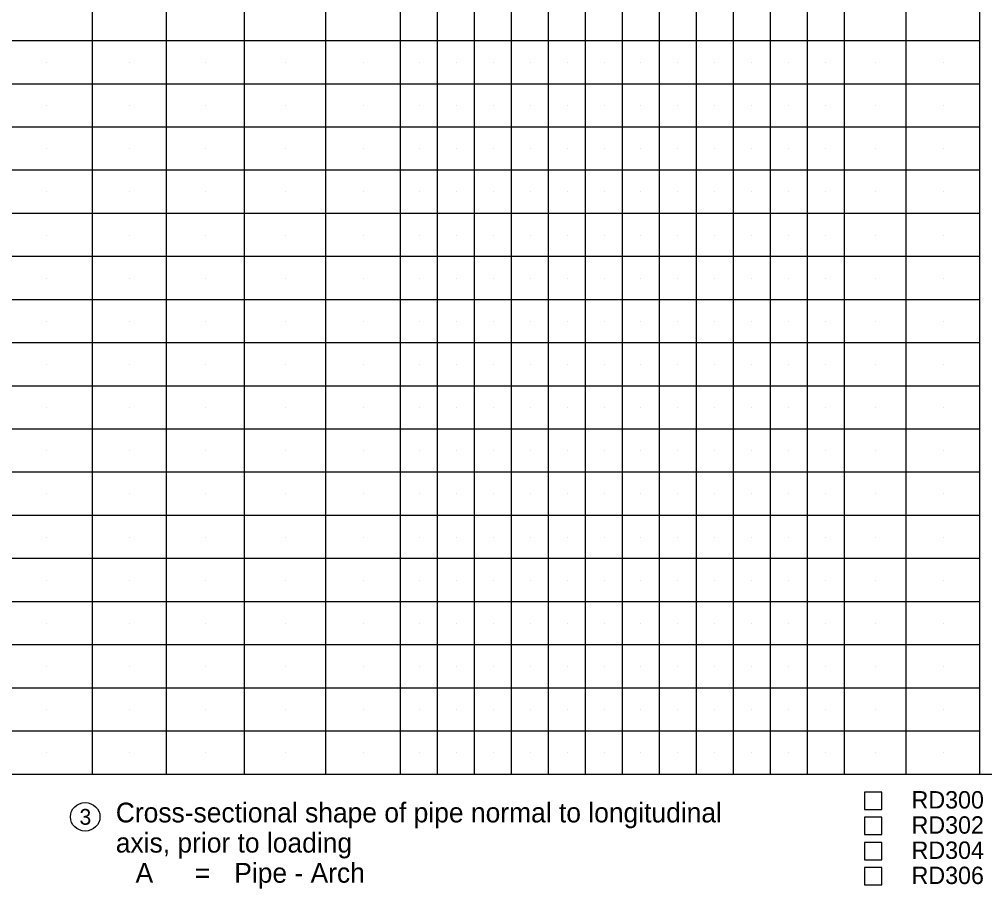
# Model space of a CAD drawing. Extents: x 0 to 1.42, y 0 to 0.92.
# Drawn here: x 0.2562 to 0.5109, y 0.2302 to 0.4596 of the extents above; entities that cross this region are included whole.
import ezdxf

# ---------------------------------------------------------------- set-up
doc = ezdxf.new("R2010")
doc.units = 0
doc.layers.add('P_ODOT_PLAN_General', color=7, linetype='Continuous')
doc.layers.add('P_RDWY_PLAN_NotesTx', color=7, linetype='Continuous')

msp = doc.modelspace()

# ---------------------------------------------------------------- linework, layer by layer
at = {"layer": 'P_ODOT_PLAN_General'}
for p, q in [((0.35681, 0.26037), (0.35681, 0.875)), ((0.50965, 0.26037), (0.50965, 0.875)), ((0.36656, 0.26037), (0.36656, 0.86199)), ((0.37632, 0.26037), (0.37632, 0.86199)), ((0.38608, 0.26037), (0.38608, 0.86199)), ((0.39583, 0.26037), (0.39583, 0.86199)), ((0.40559, 0.26037), (0.40559, 0.86199)), ((0.41534, 0.26037), (0.41534, 0.86199)), ((0.4251, 0.26037), (0.4251, 0.86199)), ((0.43486, 0.26037), (0.43486, 0.86199)), ((0.44461, 0.26037), (0.44461, 0.86199)), ((0.45437, 0.26037), (0.45437, 0.86199)), ((0.46412, 0.26037), (0.46412, 0.86199)), ((0.47388, 0.26037), (0.47388, 0.86199)), ((0.49014, 0.26037), (0.49014, 0.86199)), ((0.27551, 0.26037), (0.27551, 0.84573)), ((0.29502, 0.26037), (0.29502, 0.84573)), ((0.33711, 0.26037), (0.33711, 0.7937)), ((0.31564, 0.26037), (0.31564, 0.76118)), ((0.50965, 0.45387), (0.25112, 0.45387)), ((0.26331, 0.44818), (0.26331, 0.44818)), ((0.28526, 0.44818), (0.28526, 0.44818)), ((0.30533, 0.44818), (0.30533, 0.44818)), ((0.32637, 0.44818), (0.32637, 0.44818)), ((0.34696, 0.44818), (0.34696, 0.44818)), ((0.36169, 0.44818), (0.36169, 0.44818)), ((0.37144, 0.44818), (0.37144, 0.44818)), ((0.3812, 0.44818), (0.3812, 0.44818)), ((0.39095, 0.44818), (0.39095, 0.44818)), ((0.40071, 0.44818), (0.40071, 0.44818)), ((0.41047, 0.44818), (0.41047, 0.44818)), ((0.42022, 0.44818), (0.42022, 0.44818)), ((0.42998, 0.44818), (0.42998, 0.44818)), ((0.43973, 0.44818), (0.43973, 0.44818)), ((0.44949, 0.44818), (0.44949, 0.44818)), ((0.45925, 0.44818), (0.45925, 0.44818)), ((0.469, 0.44818), (0.469, 0.44818)), ((0.48201, 0.44818), (0.48201, 0.44818)), ((0.4999, 0.44818), (0.4999, 0.44818)), ((0.50965, 0.44248), (0.25112, 0.44248)), ((0.26331, 0.43679), (0.26331, 0.43679)), ((0.28526, 0.43679), (0.28526, 0.43679)), ((0.30533, 0.43679), (0.30533, 0.43679)), ((0.32637, 0.43679), (0.32637, 0.43679)), ((0.34696, 0.43679), (0.34696, 0.43679)), ((0.36169, 0.43679), (0.36169, 0.43679)), ((0.37144, 0.43679), (0.37144, 0.43679)), ((0.3812, 0.43679), (0.3812, 0.43679)), ((0.39095, 0.43679), (0.39095, 0.43679)), ((0.40071, 0.43679), (0.40071, 0.43679)), ((0.41047, 0.43679), (0.41047, 0.43679)), ((0.42022, 0.43679), (0.42022, 0.43679)), ((0.42998, 0.43679), (0.42998, 0.43679)), ((0.43973, 0.43679), (0.43973, 0.43679)), ((0.44949, 0.43679), (0.44949, 0.43679)), ((0.45925, 0.43679), (0.45925, 0.43679)), ((0.469, 0.43679), (0.469, 0.43679)), ((0.48201, 0.43679), (0.48201, 0.43679)), ((0.4999, 0.43679), (0.4999, 0.43679)), ((0.50965, 0.4311), (0.25112, 0.4311)), ((0.26331, 0.42541), (0.26331, 0.42541)), ((0.28526, 0.42541), (0.28526, 0.42541)), ((0.30533, 0.42541), (0.30533, 0.42541)), ((0.32637, 0.42541), (0.32637, 0.42541)), ((0.34696, 0.42541), (0.34696, 0.42541)), ((0.36169, 0.42541), (0.36169, 0.42541)), ((0.37144, 0.42541), (0.37144, 0.42541)), ((0.3812, 0.42541), (0.3812, 0.42541)), ((0.39095, 0.42541), (0.39095, 0.42541)), ((0.40071, 0.42541), (0.40071, 0.42541)), ((0.41047, 0.42541), (0.41047, 0.42541)), ((0.42022, 0.42541), (0.42022, 0.42541)), ((0.42998, 0.42541), (0.42998, 0.42541)), ((0.43973, 0.42541), (0.43973, 0.42541)), ((0.44949, 0.42541), (0.44949, 0.42541)), ((0.45925, 0.42541), (0.45925, 0.42541)), ((0.469, 0.42541), (0.469, 0.42541)), ((0.48201, 0.42541), (0.48201, 0.42541)), ((0.4999, 0.42541), (0.4999, 0.42541)), ((0.50965, 0.41972), (0.25112, 0.41972)), ((0.26331, 0.41403), (0.26331, 0.41403)), ((0.28526, 0.41403), (0.28526, 0.41403)), ((0.30533, 0.41403), (0.30533, 0.41403)), ((0.32637, 0.41403), (0.32637, 0.41403)), ((0.34696, 0.41403), (0.34696, 0.41403)), ((0.36169, 0.41403), (0.36169, 0.41403)), ((0.37144, 0.41403), (0.37144, 0.41403)), ((0.3812, 0.41403), (0.3812, 0.41403)), ((0.39095, 0.41403), (0.39095, 0.41403)), ((0.40071, 0.41403), (0.40071, 0.41403)), ((0.41047, 0.41403), (0.41047, 0.41403)), ((0.42022, 0.41403), (0.42022, 0.41403)), ((0.42998, 0.41403), (0.42998, 0.41403)), ((0.43973, 0.41403), (0.43973, 0.41403)), ((0.44949, 0.41403), (0.44949, 0.41403)), ((0.45925, 0.41403), (0.45925, 0.41403)), ((0.469, 0.41403), (0.469, 0.41403)), ((0.48201, 0.41403), (0.48201, 0.41403)), ((0.4999, 0.41403), (0.4999, 0.41403)), ((0.50965, 0.40834), (0.25112, 0.40834)), ((0.26331, 0.40265), (0.26331, 0.40265)), ((0.28526, 0.40265), (0.28526, 0.40265)), ((0.30533, 0.40265), (0.30533, 0.40265)), ((0.32637, 0.40265), (0.32637, 0.40265)), ((0.34696, 0.40265), (0.34696, 0.40265)), ((0.36169, 0.40265), (0.36169, 0.40265)), ((0.37144, 0.40265), (0.37144, 0.40265)), ((0.3812, 0.40265), (0.3812, 0.40265)), ((0.39095, 0.40265), (0.39095, 0.40265)), ((0.40071, 0.40265), (0.40071, 0.40265)), ((0.41047, 0.40265), (0.41047, 0.40265)), ((0.42022, 0.40265), (0.42022, 0.40265)), ((0.42998, 0.40265), (0.42998, 0.40265)), ((0.43973, 0.40265), (0.43973, 0.40265)), ((0.44949, 0.40265), (0.44949, 0.40265)), ((0.45925, 0.40265), (0.45925, 0.40265)), ((0.469, 0.40265), (0.469, 0.40265)), ((0.48201, 0.40265), (0.48201, 0.40265)), ((0.4999, 0.40265), (0.4999, 0.40265)), ((0.50965, 0.39696), (0.25112, 0.39696)), ((0.26331, 0.39127), (0.26331, 0.39127)), ((0.28526, 0.39127), (0.28526, 0.39127)), ((0.30533, 0.39127), (0.30533, 0.39127)), ((0.32637, 0.39127), (0.32637, 0.39127)), ((0.34696, 0.39127), (0.34696, 0.39127)), ((0.36169, 0.39127), (0.36169, 0.39127)), ((0.37144, 0.39127), (0.37144, 0.39127)), ((0.3812, 0.39127), (0.3812, 0.39127)), ((0.39095, 0.39127), (0.39095, 0.39127)), ((0.40071, 0.39127), (0.40071, 0.39127)), ((0.41047, 0.39127), (0.41047, 0.39127)), ((0.42022, 0.39127), (0.42022, 0.39127)), ((0.42998, 0.39127), (0.42998, 0.39127)), ((0.43973, 0.39127), (0.43973, 0.39127)), ((0.44949, 0.39127), (0.44949, 0.39127)), ((0.45925, 0.39127), (0.45925, 0.39127)), ((0.469, 0.39127), (0.469, 0.39127)), ((0.48201, 0.39127), (0.48201, 0.39127)), ((0.4999, 0.39127), (0.4999, 0.39127)), ((0.50965, 0.38557), (0.25112, 0.38557)), ((0.26331, 0.37988), (0.26331, 0.37988)), ((0.28526, 0.37988), (0.28526, 0.37988)), ((0.30533, 0.37988), (0.30533, 0.37988)), ((0.32637, 0.37988), (0.32637, 0.37988)), ((0.34696, 0.37988), (0.34696, 0.37988)), ((0.36169, 0.37988), (0.36169, 0.37988)), ((0.37144, 0.37988), (0.37144, 0.37988)), ((0.3812, 0.37988), (0.3812, 0.37988)), ((0.39095, 0.37988), (0.39095, 0.37988)), ((0.40071, 0.37988), (0.40071, 0.37988)), ((0.41047, 0.37988), (0.41047, 0.37988)), ((0.42022, 0.37988), (0.42022, 0.37988)), ((0.42998, 0.37988), (0.42998, 0.37988)), ((0.43973, 0.37988), (0.43973, 0.37988)), ((0.44949, 0.37988), (0.44949, 0.37988)), ((0.45925, 0.37988), (0.45925, 0.37988)), ((0.469, 0.37988), (0.469, 0.37988)), ((0.48201, 0.37988), (0.48201, 0.37988)), ((0.4999, 0.37988), (0.4999, 0.37988)), ((0.50965, 0.37419), (0.25112, 0.37419)), ((0.26331, 0.3685), (0.26331, 0.3685)), ((0.28526, 0.3685), (0.28526, 0.3685)), ((0.30533, 0.3685), (0.30533, 0.3685)), ((0.32637, 0.3685), (0.32637, 0.3685)), ((0.34696, 0.3685), (0.34696, 0.3685)), ((0.36169, 0.3685), (0.36169, 0.3685)), ((0.37144, 0.3685), (0.37144, 0.3685)), ((0.3812, 0.3685), (0.3812, 0.3685)), ((0.39095, 0.3685), (0.39095, 0.3685)), ((0.40071, 0.3685), (0.40071, 0.3685)), ((0.41047, 0.3685), (0.41047, 0.3685)), ((0.42022, 0.3685), (0.42022, 0.3685)), ((0.42998, 0.3685), (0.42998, 0.3685)), ((0.43973, 0.3685), (0.43973, 0.3685)), ((0.44949, 0.3685), (0.44949, 0.3685)), ((0.45925, 0.3685), (0.45925, 0.3685)), ((0.469, 0.3685), (0.469, 0.3685)), ((0.48201, 0.3685), (0.48201, 0.3685)), ((0.4999, 0.3685), (0.4999, 0.3685)), ((0.50965, 0.36281), (0.25112, 0.36281)), ((0.26331, 0.35712), (0.26331, 0.35712)), ((0.28526, 0.35712), (0.28526, 0.35712)), ((0.30533, 0.35712), (0.30533, 0.35712)), ((0.32637, 0.35712), (0.32637, 0.35712)), ((0.34696, 0.35712), (0.34696, 0.35712)), ((0.36169, 0.35712), (0.36169, 0.35712)), ((0.37144, 0.35712), (0.37144, 0.35712)), ((0.3812, 0.35712), (0.3812, 0.35712)), ((0.39095, 0.35712), (0.39095, 0.35712)), ((0.40071, 0.35712), (0.40071, 0.35712)), ((0.41047, 0.35712), (0.41047, 0.35712)), ((0.42022, 0.35712), (0.42022, 0.35712)), ((0.42998, 0.35712), (0.42998, 0.35712)), ((0.43973, 0.35712), (0.43973, 0.35712)), ((0.44949, 0.35712), (0.44949, 0.35712)), ((0.45925, 0.35712), (0.45925, 0.35712)), ((0.469, 0.35712), (0.469, 0.35712)), ((0.48201, 0.35712), (0.48201, 0.35712)), ((0.4999, 0.35712), (0.4999, 0.35712)), ((0.50965, 0.35143), (0.25112, 0.35143)), ((0.26331, 0.34574), (0.26331, 0.34574)), ((0.28526, 0.34574), (0.28526, 0.34574)), ((0.30533, 0.34574), (0.30533, 0.34574)), ((0.32637, 0.34574), (0.32637, 0.34574)), ((0.34696, 0.34574), (0.34696, 0.34574)), ((0.36169, 0.34574), (0.36169, 0.34574)), ((0.37144, 0.34574), (0.37144, 0.34574)), ((0.3812, 0.34574), (0.3812, 0.34574)), ((0.39095, 0.34574), (0.39095, 0.34574)), ((0.40071, 0.34574), (0.40071, 0.34574)), ((0.41047, 0.34574), (0.41047, 0.34574)), ((0.42022, 0.34574), (0.42022, 0.34574)), ((0.42998, 0.34574), (0.42998, 0.34574)), ((0.43973, 0.34574), (0.43973, 0.34574)), ((0.44949, 0.34574), (0.44949, 0.34574)), ((0.45925, 0.34574), (0.45925, 0.34574)), ((0.469, 0.34574), (0.469, 0.34574)), ((0.48201, 0.34574), (0.48201, 0.34574)), ((0.4999, 0.34574), (0.4999, 0.34574)), ((0.50965, 0.34005), (0.25112, 0.34005)), ((0.26331, 0.33436), (0.26331, 0.33436)), ((0.28526, 0.33436), (0.28526, 0.33436)), ((0.30533, 0.33436), (0.30533, 0.33436)), ((0.32637, 0.33436), (0.32637, 0.33436)), ((0.34696, 0.33436), (0.34696, 0.33436)), ((0.36169, 0.33436), (0.36169, 0.33436)), ((0.37144, 0.33436), (0.37144, 0.33436)), ((0.3812, 0.33436), (0.3812, 0.33436)), ((0.39095, 0.33436), (0.39095, 0.33436)), ((0.40071, 0.33436), (0.40071, 0.33436)), ((0.41047, 0.33436), (0.41047, 0.33436)), ((0.42022, 0.33436), (0.42022, 0.33436)), ((0.42998, 0.33436), (0.42998, 0.33436)), ((0.43973, 0.33436), (0.43973, 0.33436)), ((0.44949, 0.33436), (0.44949, 0.33436)), ((0.45925, 0.33436), (0.45925, 0.33436)), ((0.469, 0.33436), (0.469, 0.33436)), ((0.48201, 0.33436), (0.48201, 0.33436)), ((0.4999, 0.33436), (0.4999, 0.33436)), ((0.50965, 0.32866), (0.25112, 0.32866)), ((0.26331, 0.32297), (0.26331, 0.32297)), ((0.28526, 0.32297), (0.28526, 0.32297)), ((0.30533, 0.32297), (0.30533, 0.32297)), ((0.32637, 0.32297), (0.32637, 0.32297)), ((0.34696, 0.32297), (0.34696, 0.32297)), ((0.36169, 0.32297), (0.36169, 0.32297)), ((0.37144, 0.32297), (0.37144, 0.32297)), ((0.3812, 0.32297), (0.3812, 0.32297)), ((0.39095, 0.32297), (0.39095, 0.32297)), ((0.40071, 0.32297), (0.40071, 0.32297)), ((0.41047, 0.32297), (0.41047, 0.32297)), ((0.42022, 0.32297), (0.42022, 0.32297)), ((0.42998, 0.32297), (0.42998, 0.32297)), ((0.43973, 0.32297), (0.43973, 0.32297)), ((0.44949, 0.32297), (0.44949, 0.32297)), ((0.45925, 0.32297), (0.45925, 0.32297)), ((0.469, 0.32297), (0.469, 0.32297)), ((0.48201, 0.32297), (0.48201, 0.32297)), ((0.4999, 0.32297), (0.4999, 0.32297)), ((0.50965, 0.31728), (0.25112, 0.31728)), ((0.26331, 0.31159), (0.26331, 0.31159)), ((0.28526, 0.31159), (0.28526, 0.31159)), ((0.30533, 0.31159), (0.30533, 0.31159)), ((0.32637, 0.31159), (0.32637, 0.31159)), ((0.34696, 0.31159), (0.34696, 0.31159)), ((0.36169, 0.31159), (0.36169, 0.31159)), ((0.37144, 0.31159), (0.37144, 0.31159)), ((0.3812, 0.31159), (0.3812, 0.31159)), ((0.39095, 0.31159), (0.39095, 0.31159)), ((0.40071, 0.31159), (0.40071, 0.31159)), ((0.41047, 0.31159), (0.41047, 0.31159)), ((0.42022, 0.31159), (0.42022, 0.31159)), ((0.42998, 0.31159), (0.42998, 0.31159)), ((0.43973, 0.31159), (0.43973, 0.31159)), ((0.44949, 0.31159), (0.44949, 0.31159)), ((0.45925, 0.31159), (0.45925, 0.31159)), ((0.469, 0.31159), (0.469, 0.31159)), ((0.48201, 0.31159), (0.48201, 0.31159)), ((0.4999, 0.31159), (0.4999, 0.31159)), ((0.50965, 0.3059), (0.25112, 0.3059)), ((0.26331, 0.30021), (0.26331, 0.30021)), ((0.28526, 0.30021), (0.28526, 0.30021)), ((0.30533, 0.30021), (0.30533, 0.30021)), ((0.32637, 0.30021), (0.32637, 0.30021)), ((0.34696, 0.30021), (0.34696, 0.30021)), ((0.36169, 0.30021), (0.36169, 0.30021)), ((0.37144, 0.30021), (0.37144, 0.30021)), ((0.3812, 0.30021), (0.3812, 0.30021)), ((0.39095, 0.30021), (0.39095, 0.30021)), ((0.40071, 0.30021), (0.40071, 0.30021)), ((0.41047, 0.30021), (0.41047, 0.30021)), ((0.42022, 0.30021), (0.42022, 0.30021)), ((0.42998, 0.30021), (0.42998, 0.30021)), ((0.43973, 0.30021), (0.43973, 0.30021)), ((0.44949, 0.30021), (0.44949, 0.30021)), ((0.45925, 0.30021), (0.45925, 0.30021)), ((0.469, 0.30021), (0.469, 0.30021)), ((0.48201, 0.30021), (0.48201, 0.30021)), ((0.4999, 0.30021), (0.4999, 0.30021)), ((0.50965, 0.29452), (0.25112, 0.29452)), ((0.26331, 0.28883), (0.26331, 0.28883)), ((0.28526, 0.28883), (0.28526, 0.28883)), ((0.30533, 0.28883), (0.30533, 0.28883)), ((0.32637, 0.28883), (0.32637, 0.28883)), ((0.34696, 0.28883), (0.34696, 0.28883)), ((0.36169, 0.28883), (0.36169, 0.28883)), ((0.37144, 0.28883), (0.37144, 0.28883)), ((0.3812, 0.28883), (0.3812, 0.28883)), ((0.39095, 0.28883), (0.39095, 0.28883)), ((0.40071, 0.28883), (0.40071, 0.28883)), ((0.41047, 0.28883), (0.41047, 0.28883)), ((0.42022, 0.28883), (0.42022, 0.28883)), ((0.42998, 0.28883), (0.42998, 0.28883)), ((0.43973, 0.28883), (0.43973, 0.28883)), ((0.44949, 0.28883), (0.44949, 0.28883)), ((0.45925, 0.28883), (0.45925, 0.28883)), ((0.469, 0.28883), (0.469, 0.28883)), ((0.48201, 0.28883), (0.48201, 0.28883)), ((0.4999, 0.28883), (0.4999, 0.28883)), ((0.50965, 0.28314), (0.25112, 0.28314)), ((0.26331, 0.27745), (0.26331, 0.27745)), ((0.28526, 0.27745), (0.28526, 0.27745)), ((0.30533, 0.27745), (0.30533, 0.27745)), ((0.32637, 0.27745), (0.32637, 0.27745)), ((0.34696, 0.27745), (0.34696, 0.27745)), ((0.36169, 0.27745), (0.36169, 0.27745)), ((0.37144, 0.27745), (0.37144, 0.27745)), ((0.3812, 0.27745), (0.3812, 0.27745)), ((0.39095, 0.27745), (0.39095, 0.27745)), ((0.40071, 0.27745), (0.40071, 0.27745)), ((0.41047, 0.27745), (0.41047, 0.27745)), ((0.42022, 0.27745), (0.42022, 0.27745)), ((0.42998, 0.27745), (0.42998, 0.27745)), ((0.43973, 0.27745), (0.43973, 0.27745)), ((0.44949, 0.27745), (0.44949, 0.27745)), ((0.45925, 0.27745), (0.45925, 0.27745)), ((0.469, 0.27745), (0.469, 0.27745)), ((0.48201, 0.27745), (0.48201, 0.27745)), ((0.4999, 0.27745), (0.4999, 0.27745)), ((0.50965, 0.27175), (0.25112, 0.27175)), ((0.26331, 0.26606), (0.26331, 0.26606)), ((0.28526, 0.26606), (0.28526, 0.26606)), ((0.30533, 0.26606), (0.30533, 0.26606)), ((0.32637, 0.26606), (0.32637, 0.26606)), ((0.34696, 0.26606), (0.34696, 0.26606)), ((0.36169, 0.26606), (0.36169, 0.26606)), ((0.37144, 0.26606), (0.37144, 0.26606)), ((0.3812, 0.26606), (0.3812, 0.26606)), ((0.39095, 0.26606), (0.39095, 0.26606)), ((0.40071, 0.26606), (0.40071, 0.26606)), ((0.41047, 0.26606), (0.41047, 0.26606)), ((0.42022, 0.26606), (0.42022, 0.26606)), ((0.42998, 0.26606), (0.42998, 0.26606)), ((0.43973, 0.26606), (0.43973, 0.26606)), ((0.44949, 0.26606), (0.44949, 0.26606)), ((0.45925, 0.26606), (0.45925, 0.26606)), ((0.469, 0.26606), (0.469, 0.26606)), ((0.48201, 0.26606), (0.48201, 0.26606)), ((0.4999, 0.26606), (0.4999, 0.26606)), ((1.39582, 0.26037), (0.0625, 0.26037)), ((1.39582, 0.26037), (0.0625, 0.26037))]:
    msp.add_line(p, q, dxfattribs=at)
at = {"layer": 'P_RDWY_PLAN_NotesTx'}
for points in [[(0.48373, 0.25567), (0.47917, 0.25567), (0.47917, 0.25111), (0.48373, 0.25111)], [(0.48373, 0.24905), (0.47917, 0.24905), (0.47917, 0.24449), (0.48373, 0.24449)], [(0.48373, 0.24243), (0.47917, 0.24243), (0.47917, 0.23787), (0.48373, 0.23787)], [(0.48373, 0.23581), (0.47917, 0.23581), (0.47917, 0.23125), (0.48373, 0.23125)]]:
    msp.add_lwpolyline(points, close=True, dxfattribs=at)
msp.add_ellipse((0.27361, 0.24917), major_axis=(0.0039, 0), ratio=0.960077, dxfattribs=at)

# ---------------------------------------------------------------- texts
for s, height, p in [('RD300', 0.004583, (0.49161, 0.25137)), ('Cross-sectional shape of pipe normal to longitudinal', 0.0052083, (0.28168, 0.2477)), ('3', 0.00417, (0.2721, 0.24708)), ('RD302', 0.004583, (0.49161, 0.24473)), ('axis, prior to loading', 0.0052083, (0.28168, 0.23974)), ('RD304', 0.004583, (0.49161, 0.23808)), ('A', 0.00521, (0.28689, 0.23179)), ('Pipe - Arch', 0.0052083, (0.31293, 0.23179)), ('=', 0.00521, (0.30251, 0.23179)), ('RD306', 0.004583, (0.49161, 0.23144))]:
    msp.add_text(s, height=height, dxfattribs=at).set_placement(p)

doc.saveas('drawing.dxf')
